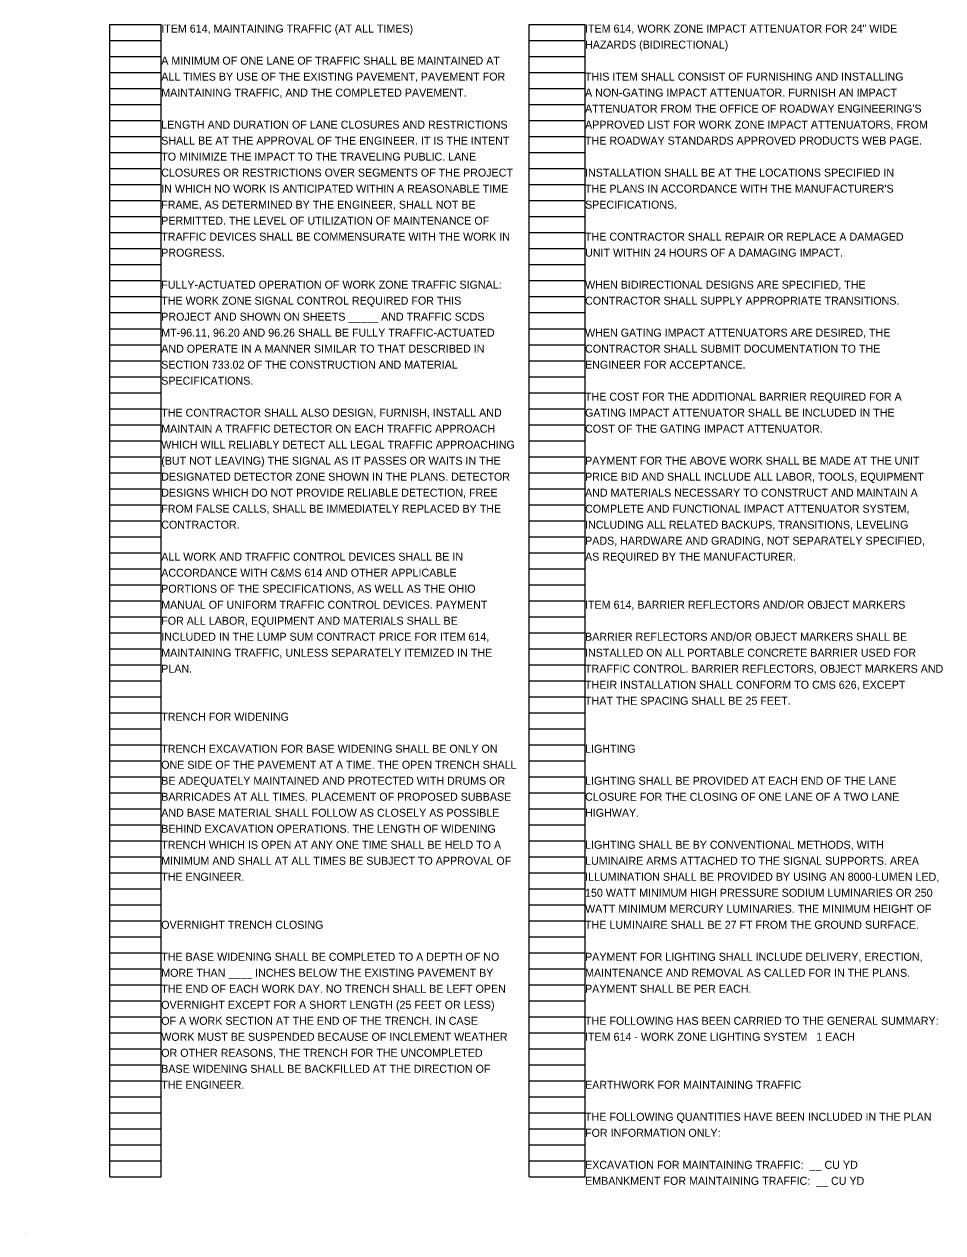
# Model space of a CAD drawing. Extents: x 0 to 74, y -29.1 to 22.
# Drawn here: x 42 to 58.08, y -29.14 to -7.99 of the extents above; entities that cross this region are included whole.
import ezdxf

# ---------------------------------------------------------------- set-up
doc = ezdxf.new("R2010")
doc.units = 0
doc.layers.add('SH_Data', color=7, linetype='Continuous')
doc.layers.add('SH_Text', color=7, linetype='Continuous')

msp = doc.modelspace()

# ---------------------------------------------------------------- linework, layer by layer
at = {"layer": 'SH_Data'}
for p, q in [((43.5, -28.16), (43.5, -8)), ((43.5, -8), (44.4, -8)), ((44.4, -28.16), (44.4, -8)), ((50.84, -28.16), (50.84, -8)), ((50.84, -8), (51.82, -8)), ((51.82, -28.16), (51.82, -8)), ((43.5, -8.28), (44.4, -8.28)), ((50.84, -8.28), (51.82, -8.28)), ((43.5, -8.56), (44.4, -8.56)), ((50.84, -8.56), (51.82, -8.56)), ((43.5, -8.84), (44.4, -8.84)), ((50.84, -8.84), (51.82, -8.84)), ((43.5, -9.12), (44.4, -9.12)), ((50.84, -9.12), (51.82, -9.12)), ((43.5, -9.4), (44.4, -9.4)), ((50.84, -9.4), (51.82, -9.4)), ((43.5, -9.68), (44.4, -9.68)), ((50.84, -9.68), (51.82, -9.68)), ((43.5, -9.96), (44.4, -9.96)), ((50.84, -9.96), (51.82, -9.96)), ((43.5, -10.24), (44.4, -10.24)), ((50.84, -10.24), (51.82, -10.24)), ((43.5, -10.52), (44.4, -10.52)), ((50.84, -10.52), (51.82, -10.52)), ((43.5, -10.8), (44.4, -10.8)), ((50.84, -10.8), (51.82, -10.8)), ((43.5, -11.08), (44.4, -11.08)), ((50.84, -11.08), (51.82, -11.08)), ((43.5, -11.36), (44.4, -11.36)), ((50.84, -11.36), (51.82, -11.36)), ((43.5, -11.64), (44.4, -11.64)), ((50.84, -11.64), (51.82, -11.64)), ((43.5, -11.92), (44.4, -11.92)), ((50.84, -11.92), (51.82, -11.92)), ((43.5, -12.2), (44.4, -12.2)), ((50.84, -12.2), (51.82, -12.2)), ((43.5, -12.48), (44.4, -12.48)), ((50.84, -12.48), (51.82, -12.48)), ((43.5, -12.76), (44.4, -12.76)), ((50.84, -12.76), (51.82, -12.76)), ((43.5, -13.04), (44.4, -13.04)), ((50.84, -13.04), (51.82, -13.04)), ((43.5, -13.32), (44.4, -13.32)), ((50.84, -13.32), (51.82, -13.32)), ((43.5, -13.6), (44.4, -13.6)), ((50.84, -13.6), (51.82, -13.6)), ((43.5, -13.88), (44.4, -13.88)), ((50.84, -13.88), (51.82, -13.88)), ((43.5, -14.16), (44.4, -14.16)), ((50.84, -14.16), (51.82, -14.16)), ((43.5, -14.44), (44.4, -14.44)), ((50.84, -14.44), (51.82, -14.44)), ((43.5, -14.72), (44.4, -14.72)), ((50.84, -14.72), (51.82, -14.72)), ((43.5, -15), (44.4, -15)), ((50.84, -15), (51.82, -15)), ((43.5, -15.28), (44.4, -15.28)), ((50.84, -15.28), (51.82, -15.28)), ((43.5, -15.56), (44.4, -15.56)), ((50.84, -15.56), (51.82, -15.56)), ((43.5, -15.84), (44.4, -15.84)), ((50.84, -15.84), (51.82, -15.84)), ((43.5, -16.12), (44.4, -16.12)), ((50.84, -16.12), (51.82, -16.12)), ((43.5, -16.4), (44.4, -16.4)), ((50.84, -16.4), (51.82, -16.4)), ((43.5, -16.68), (44.4, -16.68)), ((50.84, -16.68), (51.82, -16.68)), ((43.5, -16.96), (44.4, -16.96)), ((50.84, -16.96), (51.82, -16.96)), ((43.5, -17.24), (44.4, -17.24)), ((50.84, -17.24), (51.82, -17.24)), ((43.5, -17.52), (44.4, -17.52)), ((50.84, -17.52), (51.82, -17.52)), ((43.5, -17.8), (44.4, -17.8)), ((50.84, -17.8), (51.82, -17.8)), ((43.5, -18.08), (44.4, -18.08)), ((50.84, -18.08), (51.82, -18.08)), ((43.5, -18.36), (44.4, -18.36)), ((50.84, -18.36), (51.82, -18.36)), ((43.5, -18.64), (44.4, -18.64)), ((50.84, -18.64), (51.82, -18.64)), ((43.5, -18.92), (44.4, -18.92)), ((50.84, -18.92), (51.82, -18.92)), ((43.5, -19.2), (44.4, -19.2)), ((50.84, -19.2), (51.82, -19.2)), ((43.5, -19.48), (44.4, -19.48)), ((50.84, -19.48), (51.82, -19.48)), ((43.5, -19.76), (44.4, -19.76)), ((50.84, -19.76), (51.82, -19.76)), ((43.5, -20.04), (44.4, -20.04)), ((50.84, -20.04), (51.82, -20.04)), ((43.5, -20.32), (44.4, -20.32)), ((50.84, -20.32), (51.82, -20.32)), ((43.5, -20.6), (44.4, -20.6)), ((50.84, -20.6), (51.82, -20.6)), ((43.5, -20.88), (44.4, -20.88)), ((50.84, -20.88), (51.82, -20.88)), ((43.5, -21.16), (44.4, -21.16)), ((50.84, -21.16), (51.82, -21.16)), ((43.5, -21.44), (44.4, -21.44)), ((50.84, -21.44), (51.82, -21.44)), ((43.5, -21.72), (44.4, -21.72)), ((50.84, -21.72), (51.82, -21.72)), ((43.5, -22), (44.4, -22)), ((50.84, -22), (51.82, -22)), ((43.5, -22.28), (44.4, -22.28)), ((50.84, -22.28), (51.82, -22.28)), ((43.5, -22.56), (44.4, -22.56)), ((50.84, -22.56), (51.82, -22.56)), ((43.5, -22.84), (44.4, -22.84)), ((50.84, -22.84), (51.82, -22.84)), ((43.5, -23.12), (44.4, -23.12)), ((50.84, -23.12), (51.82, -23.12)), ((43.5, -23.4), (44.4, -23.4)), ((50.84, -23.4), (51.82, -23.4)), ((43.5, -23.68), (44.4, -23.68)), ((50.84, -23.68), (51.82, -23.68)), ((43.5, -23.96), (44.4, -23.96)), ((50.84, -23.96), (51.82, -23.96)), ((43.5, -24.24), (44.4, -24.24)), ((50.84, -24.24), (51.82, -24.24)), ((43.5, -24.52), (44.4, -24.52)), ((50.84, -24.52), (51.82, -24.52)), ((43.5, -24.8), (44.4, -24.8)), ((50.84, -24.8), (51.82, -24.8)), ((43.5, -25.08), (44.4, -25.08)), ((50.84, -25.08), (51.82, -25.08)), ((43.5, -25.36), (44.4, -25.36)), ((50.84, -25.36), (51.82, -25.36)), ((43.5, -25.64), (44.4, -25.64)), ((50.84, -25.64), (51.82, -25.64)), ((43.5, -25.92), (44.4, -25.92)), ((50.84, -25.92), (51.82, -25.92)), ((43.5, -26.2), (44.4, -26.2)), ((50.84, -26.2), (51.82, -26.2)), ((43.5, -26.48), (44.4, -26.48)), ((50.84, -26.48), (51.82, -26.48)), ((43.5, -26.76), (44.4, -26.76)), ((50.84, -26.76), (51.82, -26.76)), ((43.5, -27.04), (44.4, -27.04)), ((50.84, -27.04), (51.82, -27.04)), ((43.5, -27.32), (44.4, -27.32)), ((50.84, -27.32), (51.82, -27.32)), ((43.5, -27.6), (44.4, -27.6)), ((50.84, -27.6), (51.82, -27.6)), ((43.5, -27.88), (44.4, -27.88)), ((50.84, -27.88), (51.82, -27.88)), ((43.5, -28.16), (44.4, -28.16)), ((50.84, -28.16), (51.82, -28.16)), ((42, -29.14), (42, -29.14))]:
    msp.add_line(p, q, dxfattribs=at)

# ---------------------------------------------------------------- texts
at = {"layer": 'SH_Text'}
for s, p in [('ITEM 614, MAINTAINING TRAFFIC (AT ALL TIMES)', (44.4, -8.14)), ('ITEM 614, WORK ZONE IMPACT ATTENUATOR FOR 24" WIDE', (51.82, -8.14)), ('HAZARDS (BIDIRECTIONAL)', (51.82, -8.42)), ('A MINIMUM OF ONE LANE OF TRAFFIC SHALL BE MAINTAINED AT ', (44.4, -8.7)), ('ALL TIMES BY USE OF THE EXISTING PAVEMENT, PAVEMENT FOR ', (44.4, -8.98)), ('THIS ITEM SHALL CONSIST OF FURNISHING AND INSTALLING', (51.82, -8.98)), ('MAINTAINING TRAFFIC, AND THE COMPLETED PAVEMENT.', (44.4, -9.26)), ('A NON-GATING IMPACT ATTENUATOR. FURNISH AN IMPACT', (51.82, -9.26)), ("ATTENUATOR FROM THE OFFICE OF ROADWAY ENGINEERING'S", (51.82, -9.54)), ('LENGTH AND DURATION OF LANE CLOSURES AND RESTRICTIONS', (44.4, -9.82)), ('APPROVED LIST FOR WORK ZONE IMPACT ATTENUATORS, FROM', (51.82, -9.82)), ('SHALL BE AT THE APPROVAL OF THE ENGINEER. IT IS THE INTENT', (44.4, -10.1)), ('THE ROADWAY STANDARDS APPROVED PRODUCTS WEB PAGE.', (51.82, -10.1)), ('TO MINIMIZE THE IMPACT TO THE TRAVELING PUBLIC. LANE', (44.4, -10.38)), ('CLOSURES OR RESTRICTIONS OVER SEGMENTS OF THE PROJECT', (44.4, -10.66)), ('INSTALLATION SHALL BE AT THE LOCATIONS SPECIFIED IN', (51.82, -10.66)), ('IN WHICH NO WORK IS ANTICIPATED WITHIN A REASONABLE TIME', (44.4, -10.94)), ("THE PLANS IN ACCORDANCE WITH THE MANUFACTURER'S", (51.82, -10.94)), ('FRAME, AS DETERMINED BY THE ENGINEER, SHALL NOT BE', (44.4, -11.22)), ('SPECIFICATIONS.', (51.82, -11.22)), ('PERMITTED. THE LEVEL OF UTILIZATION OF MAINTENANCE OF', (44.4, -11.5)), ('TRAFFIC DEVICES SHALL BE COMMENSURATE WITH THE WORK IN', (44.4, -11.78)), ('THE CONTRACTOR SHALL REPAIR OR REPLACE A DAMAGED', (51.82, -11.78)), ('PROGRESS.', (44.4, -12.06)), ('UNIT WITHIN 24 HOURS OF A DAMAGING IMPACT.', (51.82, -12.06)), ('FULLY-ACTUATED OPERATION OF WORK ZONE TRAFFIC SIGNAL:', (44.4, -12.62)), ('WHEN BIDIRECTIONAL DESIGNS ARE SPECIFIED, THE', (51.82, -12.62)), ('THE WORK ZONE SIGNAL CONTROL REQUIRED FOR THIS', (44.4, -12.9)), ('CONTRACTOR SHALL SUPPLY APPROPRIATE TRANSITIONS.', (51.82, -12.9)), ('PROJECT AND SHOWN ON SHEETS _____ AND TRAFFIC SCDS', (44.4, -13.18)), ('MT-96.11, 96.20 AND 96.26 SHALL BE FULLY TRAFFIC-ACTUATED', (44.4, -13.46)), ('WHEN GATING IMPACT ATTENUATORS ARE DESIRED, THE', (51.82, -13.46)), ('AND OPERATE IN A MANNER SIMILAR TO THAT DESCRIBED IN', (44.4, -13.74)), ('CONTRACTOR SHALL SUBMIT DOCUMENTATION TO THE', (51.82, -13.74)), ('SECTION 733.02 OF THE CONSTRUCTION AND MATERIAL', (44.4, -14.02)), ('ENGINEER FOR ACCEPTANCE.', (51.82, -14.02)), ('SPECIFICATIONS.', (44.4, -14.3)), ('THE COST FOR THE ADDITIONAL BARRIER REQUIRED FOR A', (51.82, -14.58)), ('THE CONTRACTOR SHALL ALSO DESIGN, FURNISH, INSTALL AND', (44.4, -14.86)), ('GATING IMPACT ATTENUATOR SHALL BE INCLUDED IN THE', (51.82, -14.86)), ('MAINTAIN A TRAFFIC DETECTOR ON EACH TRAFFIC APPROACH', (44.4, -15.14)), ('COST OF THE GATING IMPACT ATTENUATOR.', (51.82, -15.14)), ('WHICH WILL RELIABLY DETECT ALL LEGAL TRAFFIC APPROACHING', (44.4, -15.42)), ('(BUT NOT LEAVING) THE SIGNAL AS IT PASSES OR WAITS IN THE', (44.4, -15.7)), ('PAYMENT FOR THE ABOVE WORK SHALL BE MADE AT THE UNIT', (51.82, -15.7)), ('DESIGNATED DETECTOR ZONE SHOWN IN THE PLANS. DETECTOR', (44.4, -15.98)), ('PRICE BID AND SHALL INCLUDE ALL LABOR, TOOLS, EQUIPMENT', (51.82, -15.98)), ('DESIGNS WHICH DO NOT PROVIDE RELIABLE DETECTION, FREE', (44.4, -16.26)), ('AND MATERIALS NECESSARY TO CONSTRUCT AND MAINTAIN A', (51.82, -16.26)), ('FROM FALSE CALLS, SHALL BE IMMEDIATELY REPLACED BY THE', (44.4, -16.54)), ('COMPLETE AND FUNCTIONAL IMPACT ATTENUATOR SYSTEM,', (51.82, -16.54)), ('CONTRACTOR.', (44.4, -16.82)), ('INCLUDING ALL RELATED BACKUPS, TRANSITIONS, LEVELING', (51.82, -16.82)), ('PADS, HARDWARE AND GRADING, NOT SEPARATELY SPECIFIED,', (51.82, -17.1)), ('ALL WORK AND TRAFFIC CONTROL DEVICES SHALL BE IN', (44.4, -17.38)), ('AS REQUIRED BY THE MANUFACTURER.', (51.82, -17.38)), ('ACCORDANCE WITH C&MS 614 AND OTHER APPLICABLE', (44.4, -17.66)), ('PORTIONS OF THE SPECIFICATIONS, AS WELL AS THE OHIO', (44.4, -17.94)), ('MANUAL OF UNIFORM TRAFFIC CONTROL DEVICES. PAYMENT', (44.4, -18.22)), ('ITEM 614, BARRIER REFLECTORS AND/OR OBJECT MARKERS', (51.82, -18.22)), ('FOR ALL LABOR, EQUIPMENT AND MATERIALS SHALL BE', (44.4, -18.5)), ('INCLUDED IN THE LUMP SUM CONTRACT PRICE FOR ITEM 614,', (44.4, -18.78)), ('BARRIER REFLECTORS AND/OR OBJECT MARKERS SHALL BE ', (51.82, -18.78)), ('MAINTAINING TRAFFIC, UNLESS SEPARATELY ITEMIZED IN THE', (44.4, -19.06)), ('INSTALLED ON ALL PORTABLE CONCRETE BARRIER USED FOR ', (51.82, -19.06)), ('PLAN.', (44.4, -19.34)), ('TRAFFIC CONTROL. BARRIER REFLECTORS, OBJECT MARKERS AND ', (51.82, -19.34)), ('THEIR INSTALLATION SHALL CONFORM TO CMS 626, EXCEPT ', (51.82, -19.62)), ('THAT THE SPACING SHALL BE 25 FEET.', (51.82, -19.9)), ('TRENCH FOR WIDENING', (44.4, -20.18)), ('TRENCH EXCAVATION FOR BASE WIDENING SHALL BE ONLY ON', (44.4, -20.74)), ('LIGHTING', (51.82, -20.74)), ('ONE SIDE OF THE PAVEMENT AT A TIME. THE OPEN TRENCH SHALL', (44.4, -21.02)), ('BE ADEQUATELY MAINTAINED AND PROTECTED WITH DRUMS OR', (44.4, -21.3)), ('LIGHTING SHALL BE PROVIDED AT EACH END OF THE LANE', (51.82, -21.3)), ('BARRICADES AT ALL TIMES. PLACEMENT OF PROPOSED SUBBASE', (44.4, -21.58)), ('CLOSURE FOR THE CLOSING OF ONE LANE OF A TWO LANE', (51.82, -21.58)), ('AND BASE MATERIAL SHALL FOLLOW AS CLOSELY AS POSSIBLE', (44.4, -21.86)), ('HIGHWAY.', (51.82, -21.86)), ('BEHIND EXCAVATION OPERATIONS. THE LENGTH OF WIDENING', (44.4, -22.14)), ('TRENCH WHICH IS OPEN AT ANY ONE TIME SHALL BE HELD TO A', (44.4, -22.42)), ('LIGHTING SHALL BE BY CONVENTIONAL METHODS, WITH', (51.82, -22.42)), ('MINIMUM AND SHALL AT ALL TIMES BE SUBJECT TO APPROVAL OF', (44.4, -22.7)), ('LUMINAIRE ARMS ATTACHED TO THE SIGNAL SUPPORTS. AREA', (51.82, -22.7)), ('THE ENGINEER.', (44.4, -22.98)), ('ILLUMINATION SHALL BE PROVIDED BY USING AN 8000-LUMEN LED,', (51.82, -22.98)), ('150 WATT MINIMUM HIGH PRESSURE SODIUM LUMINARIES OR 250', (51.82, -23.26)), ('WATT MINIMUM MERCURY LUMINARIES. THE MINIMUM HEIGHT OF', (51.82, -23.54)), ('OVERNIGHT TRENCH CLOSING', (44.4, -23.82)), ('THE LUMINAIRE SHALL BE 27 FT FROM THE GROUND SURFACE.', (51.82, -23.82)), ('THE BASE WIDENING SHALL BE COMPLETED TO A DEPTH OF NO', (44.4, -24.38)), ('PAYMENT FOR LIGHTING SHALL INCLUDE DELIVERY, ERECTION,', (51.82, -24.38)), ('MORE THAN ____ INCHES BELOW THE EXISTING PAVEMENT BY', (44.4, -24.66)), ('MAINTENANCE AND REMOVAL AS CALLED FOR IN THE PLANS.', (51.82, -24.66)), ('THE END OF EACH WORK DAY. NO TRENCH SHALL BE LEFT OPEN', (44.4, -24.94)), ('PAYMENT SHALL BE PER EACH.', (51.82, -24.94)), ('OVERNIGHT EXCEPT FOR A SHORT LENGTH (25 FEET OR LESS)', (44.4, -25.22)), ('OF A WORK SECTION AT THE END OF THE TRENCH. IN CASE', (44.4, -25.5)), ('THE FOLLOWING HAS BEEN CARRIED TO THE GENERAL SUMMARY:', (51.82, -25.5)), ('WORK MUST BE SUSPENDED BECAUSE OF INCLEMENT WEATHER', (44.4, -25.78)), ('ITEM 614 - WORK ZONE LIGHTING SYSTEM   1 EACH', (51.82, -25.78)), ('OR OTHER REASONS, THE TRENCH FOR THE UNCOMPLETED', (44.4, -26.06)), ('BASE WIDENING SHALL BE BACKFILLED AT THE DIRECTION OF', (44.4, -26.34)), ('THE ENGINEER.', (44.4, -26.62)), ('EARTHWORK FOR MAINTAINING TRAFFIC', (51.82, -26.62)), ('THE FOLLOWING QUANTITIES HAVE BEEN INCLUDED IN THE PLAN ', (51.82, -27.18)), ('FOR INFORMATION ONLY:', (51.82, -27.46)), ('EXCAVATION FOR MAINTAINING TRAFFIC:  __ CU YD', (51.82, -28.02)), ('EMBANKMENT FOR MAINTAINING TRAFFIC:  __ CU YD', (51.82, -28.3))]:
    msp.add_text(s, height=0.14, dxfattribs=at).set_placement(p)

doc.saveas('drawing.dxf')
